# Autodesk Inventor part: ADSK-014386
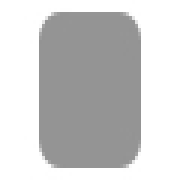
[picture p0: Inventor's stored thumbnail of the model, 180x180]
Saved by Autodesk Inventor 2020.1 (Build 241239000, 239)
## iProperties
Created: 2019-01
Part Number: ADSK-014386
Material: Stahl, weich
Document SubType Name: Modeling
Designer: lutzd
Language: de-DE
Size Designation: 5 x 60 x 40
Categories: <MemberInstance><Categories><Category DisplayName="Sonstige Bauteile" InternalName="5aa15e00-363f-49f2-933f-16f664388e3f" Mnemonic="OTHER"><Category DisplayName
Mass: 93.3577 g
Surface Area: 57.1416 cm^2
Volume: 11.8927 cm^3
Density: 7.85 g/cm^3
Appearance: Semi-Polished(8)
IsCustomPart: 1
Title: end cap
Author: lutzd
Revision Number: -
DocNumber: ADSK-014386
Folder: 01 - Themengebiete\Simplification\01 - Packaging machine\
VDS_Category: 3D Komponenten
VDS_NumSchm: Autodesk
Mass: 0,093 kg
VLT_Material: Stahl, weich
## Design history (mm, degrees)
sketch "Sketch1"
  geometry: L1 (0, 20.175)-(0, -21.446); L2 (-20.203, 0)-(20.169, 0); L3 (-20, 30)-(20, 30); L4 (20, 30)-(20, -30); L5 (20, -30)-(-20, -30); L6 (-20, -30)-(-20, 30); 1 further point
  constraints: 12 end point, 2 horizontal, 2 parallel, 2 point on line, 1 perpendicular, 1 vertical
  dimensions: "d0" = 60 distance between parallel lines of L5 L3 (= height); "d1" = 30 distance between parallel lines of L2 L3 (= 0.5 x height); "d2" = 40 distance between parallel lines of L6 L4 (= width); "d3" = 20 distance between parallel lines of L6 L1 (= 0.5 x width)
extrude "Extrusion1" new body sketch "Sketch1" distance "d4" = 5 (= thickness); taper "d5" = 0 deg
fillet "Fillet1" dims "d6" = 5 (= fillet), "d7" = 0, "fillet" = 5 [user parameter; used in 1 equation term]
chamfer "Chamfer1" distance "d8" = 0 (computed from chamfer); stored, may be unused: second distance "d9" = 2, angle "d10" = 45 deg; dims "d11" = 0, "chamfer" = 0 [user parameter; used in 1 equation term]
body "Solid1"
other parameters: "thickness" = 5 [user parameter; used in 1 equation term], "width" = 40 [user parameter; used in 2 equation terms], "height" = 60 [user parameter; used in 2 equation terms]
